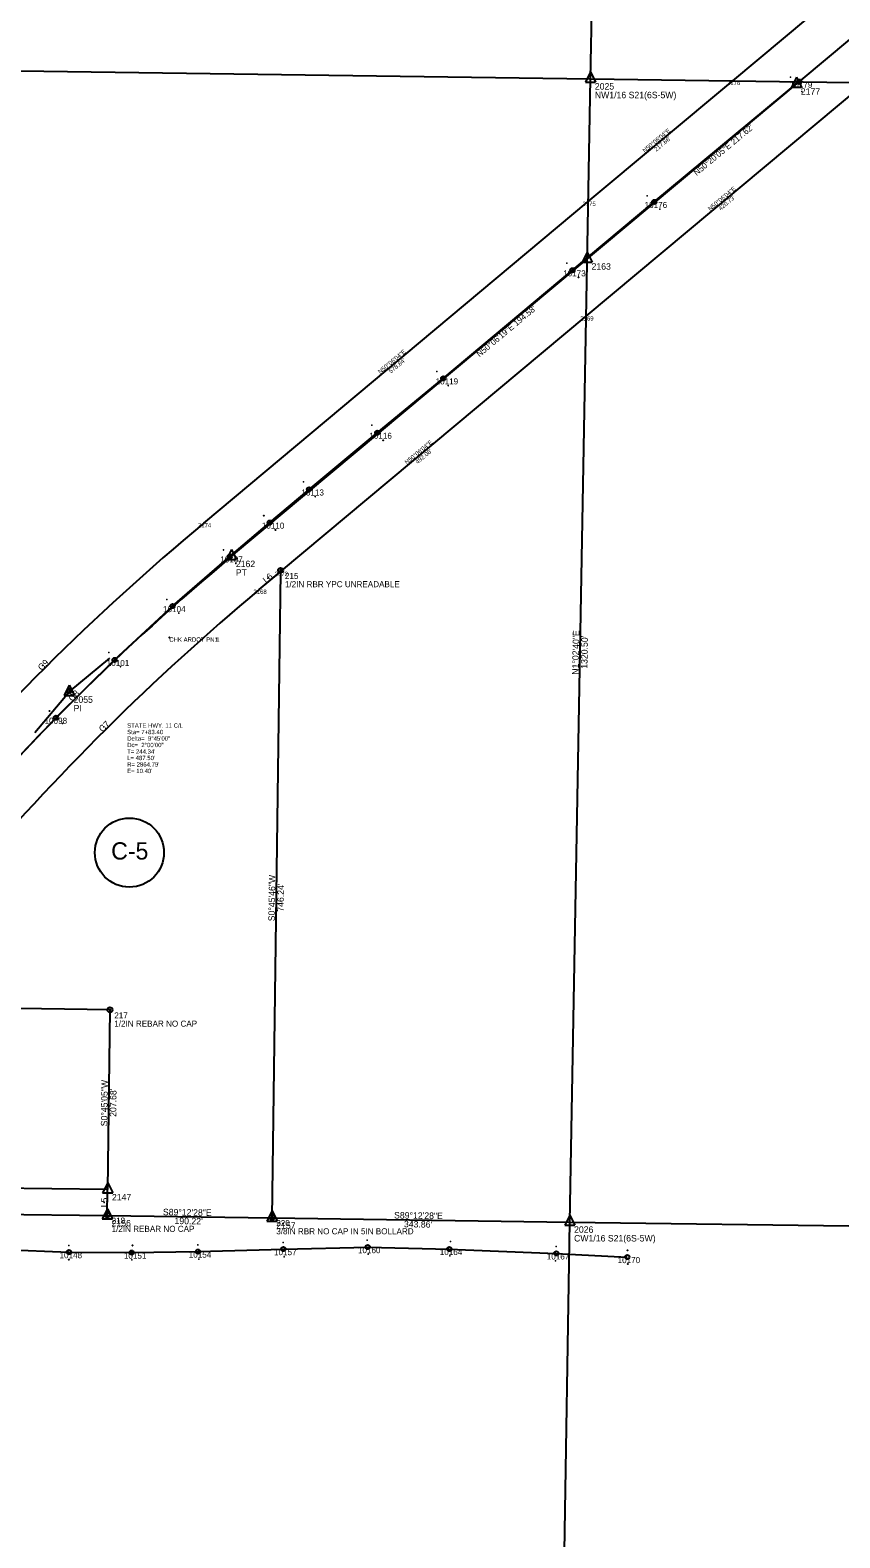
# Model space of a CAD drawing. Extents: x 1431802 to 1457777, y 1852108 to 1876350.
# Drawn here: x 1444444 to 1445379, y 1854558 to 1856299 of the extents above; entities that cross this region are included whole.
import ezdxf

# ---------------------------------------------------------------- set-up
doc = ezdxf.new("R2010")
doc.units = 0
for name, color, linetype in [('Default', 7, 'Continuous'), ('S_CAL_CORNER', 7, 'Continuous'), ('S_CAL_CORNER_ANNOT', 7, 'Continuous'), ('S_EXIST_ROW', 7, 'Continuous'), ('S_EXIST_ROW_ANNOT', 7, 'Continuous'), ('S_EXISTING_ALIGNMENT', 7, 'Continuous'), ('S_EXISTING_ALIGNMENT_ANNOT', 7, 'Continuous'), ('S_IRON_PIN', 7, 'Continuous'), ('S_IRON_PIN_ANNOT', 7, 'Continuous'), ('S_MSC_PT_SYM', 7, 'Continuous'), ('S_PROPERTY', 7, 'Continuous'), ('S_PROPERTY_ANNOT', 7, 'Continuous'), ('S_QSECTION', 7, 'Continuous'), ('S_QSECTION_ANNOT', 7, 'Continuous'), ('S_RDW_PT_SYM', 7, 'Continuous'), ('S_SIXTEEN_SECTION', 7, 'Continuous'), ('S_SIXTEEN_SECTION_ANNOT', 7, 'Continuous'), ('S_SURVEY_TEXT_ANNOT', 7, 'Continuous')]:
    doc.layers.add(name, color=color, linetype=linetype)

msp = doc.modelspace()

# ---------------------------------------------------------------- linework, layer by layer
at = {"layer": 'Default'}
for points in [[(1444718.8, 1855665.9), (1444718.8, 1855665.9), (1444718.8, 1855665.9), (1444718.8, 1855665.9), (1444718.8, 1855665.9), (1444718.8, 1855665.8), (1444718.8, 1855665.9), (1444718.8, 1855665.9)], [(1444449.8, 1855487.8), (1444489.4, 1855534.4), (1444536.3, 1855573.6)], [(1444458.9, 1855565.1), (1444458.8, 1855565.2), (1444458.9, 1855565.1), (1444458.8, 1855565.1), (1444458.9, 1855565.1), (1444458.9, 1855565.1), (1444458.9, 1855565.1), (1444458.9, 1855565.2)], [(1444494.1, 1855529.7), (1444494, 1855529.7), (1444494.1, 1855529.7), (1444494, 1855529.6), (1444494.1, 1855529.7), (1444494.1, 1855529.6), (1444494.1, 1855529.7), (1444494.1, 1855529.7)], [(1444529.3, 1855494.2), (1444529.3, 1855494.2), (1444529.3, 1855494.2), (1444529.3, 1855494.1), (1444529.3, 1855494.2), (1444529.3, 1855494.1), (1444529.3, 1855494.2), (1444529.3, 1855494.2)], [(1444529.8, 1854944.8), (1444529.7, 1854944.8), (1444529.8, 1854944.8), (1444529.8, 1854944.7), (1444529.8, 1854944.8), (1444529.8, 1854944.8), (1444529.8, 1854944.8), (1444529.8, 1854944.8)]]:
    msp.add_lwpolyline(points, dxfattribs=at)
msp.add_lwpolyline([(1444491.2, 1855532.6), (1444485.9, 1855534.4), (1444489.4, 1855537.9)], close=True, dxfattribs=at)
at = {"layer": 'S_CAL_CORNER'}
for p, q in [((1445091.5, 1856250.6), (1445085.6, 1856238.8)), ((1445091.5, 1856250.6), (1445085.6, 1856238.8)), ((1445091.5, 1856250.6), (1445097.3, 1856238.8)), ((1445091.5, 1856250.6), (1445097.3, 1856238.8)), ((1445329.4, 1856244.6), (1445323.5, 1856232.8)), ((1445329.4, 1856244.6), (1445335.2, 1856232.8)), ((1445085.6, 1856238.8), (1445097.3, 1856238.8)), ((1445085.6, 1856238.8), (1445097.3, 1856238.8)), ((1445323.5, 1856232.8), (1445335.2, 1856232.8)), ((1445087.7, 1856042.5), (1445081.8, 1856030.7)), ((1445087.7, 1856042.5), (1445093.5, 1856030.7)), ((1445081.8, 1856030.7), (1445093.5, 1856030.7)), ((1444676.9, 1855699.1), (1444671.1, 1855687.3)), ((1444671.1, 1855687.3), (1444682.7, 1855687.3)), ((1444676.9, 1855699.1), (1444682.7, 1855687.3)), ((1444489.5, 1855542.4), (1444483.6, 1855530.5)), ((1444483.6, 1855530.5), (1444495.3, 1855530.5)), ((1444489.5, 1855542.4), (1444495.3, 1855530.5)), ((1444533.8, 1854967.7), (1444527.9, 1854955.9)), ((1444527.9, 1854955.9), (1444539.6, 1854955.9)), ((1444533.8, 1854967.7), (1444539.6, 1854955.9)), ((1444533.4, 1854937.7), (1444527.5, 1854925.9)), ((1444533.4, 1854937.7), (1444539.2, 1854925.9)), ((1444723.6, 1854935.1), (1444717.7, 1854923.3)), ((1444723.6, 1854935.1), (1444729.4, 1854923.3)), ((1444527.5, 1854925.9), (1444539.2, 1854925.9)), ((1444717.7, 1854923.3), (1444729.4, 1854923.3)), ((1445067.4, 1854930.3), (1445061.6, 1854918.5)), ((1445061.6, 1854918.5), (1445073.3, 1854918.5)), ((1445067.4, 1854930.3), (1445073.3, 1854918.5))]:
    msp.add_line(p, q, dxfattribs=at)
at = {"layer": 'S_EXIST_ROW'}
for p, q in [((1445255.8, 1856240.4), (1446439.4, 1857229.9)), ((1445086.4, 1855968.4), (1445409.2, 1856238.3)), ((1445088.8, 1856100.7), (1445255.8, 1856240.4)), ((1444644.8, 1855729.5), (1445088.8, 1856100.7)), ((1444708.9, 1855652.7), (1445086.4, 1855968.4))]:
    msp.add_line(p, q, dxfattribs=at)
for radius, end in [(2914.8, 139.6489), (2814.8, 139.649)]:
    msp.add_arc((1446514.4, 1853493.3), radius, 129.899, end, dxfattribs=at)
at = {"layer": 'S_EXISTING_ALIGNMENT'}
for p, q in [((1444676.8, 1855691.1), (1446438.4, 1857164)), ((1445165, 1856100.4), (1445332.5, 1856239.3)), ((1445070.6, 1856021.4), (1445165, 1856100.4)), ((1444921.4, 1855896.6), (1445070.6, 1856021.4)), ((1444845.1, 1855833.8), (1444921.4, 1855896.6)), ((1444766.4, 1855768.3), (1444845.1, 1855833.8)), ((1444721, 1855730), (1444766.4, 1855768.3)), ((1444674.9, 1855691), (1444721, 1855730)), ((1444608.8, 1855633.6), (1444674.9, 1855691)), ((1444541.8, 1855571.4), (1444608.8, 1855633.6)), ((1444474, 1855504.7), (1444541.8, 1855571.4)), ((1444410.9, 1855438.1), (1444474, 1855504.7)), ((1444413.9, 1854890.7), (1444489, 1854887.5)), ((1444489, 1854887.5), (1444561.4, 1854886.9)), ((1444561.4, 1854886.9), (1444638.2, 1854888.1)), ((1444638.2, 1854888.1), (1444736.7, 1854891)), ((1444736.7, 1854891), (1444834.1, 1854893.3)), ((1444834.1, 1854893.3), (1444928.3, 1854891.1)), ((1444928.3, 1854891.1), (1445051.9, 1854886)), ((1445051.9, 1854886), (1445133.8, 1854881.8))]:
    msp.add_line(p, q, dxfattribs=at)
for centre in [(1445332.5, 1856239.3), (1445165, 1856100.4), (1445070.6, 1856021.4), (1444921.4, 1855896.6), (1444845.1, 1855833.8), (1444766.4, 1855768.3), (1444721, 1855730), (1444674.9, 1855691), (1444608.8, 1855633.6), (1444541.8, 1855571.4), (1444474, 1855504.7), (1444489, 1854887.5), (1444561.4, 1854886.9), (1444638.2, 1854888.1), (1444736.7, 1854891), (1444834.1, 1854893.3), (1444928.3, 1854891.1), (1445051.9, 1854886), (1445133.8, 1854881.8)]:
    msp.add_circle(centre, 2.5, dxfattribs=at)
msp.add_arc((1446514.4, 1853493.3), 2864.8, 129.899, 139.649, dxfattribs=at)
at = {"layer": 'S_IRON_PIN'}
for centre, radius in [((1444733.5, 1855674.9), 2.91), ((1444733.5, 1855674.9), 0.411), ((1444733.5, 1855674.9), 0.262), ((1444733.5, 1855674.9), 0.212), ((1444733.5, 1855674.9), 0.145), ((1444733.5, 1855674.9), 0.0581), ((1444733.5, 1855674.9), 0.0822), ((1444536.4, 1855167.4), 2.91), ((1444536.4, 1855167.4), 0.411), ((1444536.4, 1855167.4), 0.262), ((1444536.4, 1855167.4), 0.212), ((1444536.4, 1855167.4), 0.145), ((1444536.4, 1855167.4), 0.0822), ((1444536.4, 1855167.4), 0.0581), ((1444533.3, 1854930.4), 2.91), ((1444533.3, 1854930.4), 0.411), ((1444533.3, 1854930.4), 0.212), ((1444533.3, 1854930.4), 0.262), ((1444533.3, 1854930.4), 0.145), ((1444533.3, 1854930.4), 0.0581), ((1444533.3, 1854930.4), 0.0822), ((1444723.5, 1854927.6), 2.91), ((1444723.5, 1854927.6), 0.411), ((1444723.5, 1854927.6), 0.262), ((1444723.5, 1854927.6), 0.212), ((1444723.5, 1854927.6), 0.145), ((1444723.5, 1854927.6), 0.0581), ((1444723.5, 1854927.6), 0.0822)]:
    msp.add_circle(centre, radius, dxfattribs=at)
at = {"layer": 'S_MSC_PT_SYM'}
for points in [[(1444605, 1855597.4), (1444605, 1855597.5), (1444605, 1855597.4), (1444604.9, 1855597.4), (1444605, 1855597.4), (1444605, 1855597.4), (1444605, 1855597.4), (1444605, 1855597.4)], [(1444605, 1855597.4), (1444605, 1855597.5), (1444605, 1855597.4), (1444604.9, 1855597.4), (1444605, 1855597.4), (1444605, 1855597.4), (1444605, 1855597.4), (1444605, 1855597.4)], [(1444605, 1855597.5), (1444605, 1855597.5), (1444605, 1855597.5), (1444605, 1855597.5), (1444605, 1855597.5), (1444605, 1855597.4), (1444605, 1855597.5), (1444605.1, 1855597.5)]]:
    msp.add_lwpolyline(points, dxfattribs=at)
at = {"layer": 'S_PROPERTY'}
for p, q in [((1444708.9, 1855652.7), (1444733.5, 1855673.3)), ((1444733.5, 1855673.3), (1444723.5, 1854927.1)), ((1444536.4, 1855167.4), (1444279.1, 1855170.8)), ((1444536.4, 1855167.4), (1444533.7, 1854959.7)), ((1444533.7, 1854959.7), (1444276.4, 1854963.3)), ((1444533.3, 1854929.7), (1444533.7, 1854959.7)), ((1444276, 1854933.3), (1444533.3, 1854929.7)), ((1444723.5, 1854927.1), (1445067.4, 1854922.3)), ((1445067.4, 1854922.3), (1446405.8, 1854903.8))]:
    msp.add_line(p, q, dxfattribs=at)
msp.add_circle((1444558.9, 1855348.9), 39.9, dxfattribs=at)
at = {"layer": 'S_QSECTION'}
msp.add_line((1444533.3, 1854929.7), (1444723.5, 1854927.1), dxfattribs=at)
at = {"layer": 'S_RDW_PT_SYM'}
for points in [[(1445322.3, 1856244.6), (1445322.3, 1856244.6), (1445322.3, 1856244.6), (1445322.3, 1856244.6), (1445322.3, 1856244.6), (1445322.3, 1856244.5), (1445322.3, 1856244.6), (1445322.4, 1856244.6)], [(1445335.3, 1856227.9), (1445335.3, 1856227.9), (1445335.3, 1856227.9), (1445335.3, 1856227.9), (1445335.3, 1856227.9), (1445335.3, 1856227.8), (1445335.3, 1856227.9), (1445335.4, 1856227.9)], [(1445156.9, 1856107.5), (1445156.9, 1856107.6), (1445156.9, 1856107.5), (1445156.9, 1856107.5), (1445156.9, 1856107.5), (1445156.9, 1856107.5), (1445156.9, 1856107.5), (1445157, 1856107.5)], [(1445171.4, 1856092), (1445171.4, 1856092.1), (1445171.4, 1856092), (1445171.3, 1856092), (1445171.4, 1856092), (1445171.4, 1856092), (1445171.4, 1856092), (1445171.4, 1856092)], [(1445064.1, 1856029.7), (1445064.1, 1856029.8), (1445064.1, 1856029.7), (1445064.1, 1856029.7), (1445064.1, 1856029.7), (1445064.1, 1856029.7), (1445064.1, 1856029.7), (1445064.2, 1856029.7)], [(1445077.6, 1856013.2), (1445077.6, 1856013.3), (1445077.6, 1856013.2), (1445077.6, 1856013.2), (1445077.6, 1856013.2), (1445077.6, 1856013.2), (1445077.6, 1856013.2), (1445077.7, 1856013.2)], [(1444913.9, 1855904.6), (1444913.9, 1855904.6), (1444913.9, 1855904.6), (1444913.8, 1855904.6), (1444913.9, 1855904.6), (1444913.9, 1855904.5), (1444913.9, 1855904.6), (1444913.9, 1855904.6)], [(1444927.2, 1855888.3), (1444927.2, 1855888.4), (1444927.2, 1855888.3), (1444927.2, 1855888.3), (1444927.2, 1855888.3), (1444927.2, 1855888.3), (1444927.2, 1855888.3), (1444927.3, 1855888.3)], [(1444838.7, 1855842.4), (1444838.7, 1855842.5), (1444838.7, 1855842.4), (1444838.7, 1855842.4), (1444838.7, 1855842.4), (1444838.7, 1855842.4), (1444838.7, 1855842.4), (1444838.8, 1855842.4)], [(1444852, 1855825.1), (1444852, 1855825.1), (1444852, 1855825.1), (1444852, 1855825.1), (1444852, 1855825.1), (1444852, 1855825), (1444852, 1855825.1), (1444852.1, 1855825.1)], [(1444760.1, 1855777), (1444760.1, 1855777.1), (1444760.1, 1855777), (1444760, 1855777), (1444760.1, 1855777), (1444760.1, 1855777), (1444760.1, 1855777), (1444760.1, 1855777)], [(1444773.6, 1855760.3), (1444773.6, 1855760.3), (1444773.6, 1855760.3), (1444773.6, 1855760.3), (1444773.6, 1855760.3), (1444773.6, 1855760.2), (1444773.6, 1855760.3), (1444773.7, 1855760.3)], [(1444714.2, 1855738.1), (1444714.2, 1855738.1), (1444714.2, 1855738.1), (1444714.1, 1855738.1), (1444714.2, 1855738.1), (1444714.2, 1855738), (1444714.2, 1855738.1), (1444714.2, 1855738.1)], [(1444727.5, 1855721.5), (1444727.5, 1855721.5), (1444727.5, 1855721.5), (1444727.4, 1855721.5), (1444727.5, 1855721.5), (1444727.5, 1855721.4), (1444727.5, 1855721.5), (1444727.5, 1855721.5)], [(1444667.7, 1855698.6), (1444667.7, 1855698.6), (1444667.7, 1855698.6), (1444667.7, 1855698.6), (1444667.7, 1855698.6), (1444667.7, 1855698.5), (1444667.7, 1855698.6), (1444667.8, 1855698.6)], [(1444681.7, 1855682.8), (1444681.7, 1855682.9), (1444681.7, 1855682.8), (1444681.6, 1855682.8), (1444681.7, 1855682.8), (1444681.7, 1855682.8), (1444681.7, 1855682.8), (1444681.7, 1855682.8)], [(1444602.1, 1855641.2), (1444602.1, 1855641.3), (1444602.1, 1855641.2), (1444602, 1855641.2), (1444602.1, 1855641.2), (1444602.1, 1855641.2), (1444602.1, 1855641.2), (1444602.1, 1855641.2)], [(1444615.8, 1855625.6), (1444615.8, 1855625.6), (1444615.8, 1855625.6), (1444615.8, 1855625.6), (1444615.8, 1855625.6), (1444615.8, 1855625.5), (1444615.8, 1855625.6), (1444615.9, 1855625.6)], [(1444535, 1855580), (1444535, 1855580), (1444535, 1855580), (1444535, 1855580), (1444535, 1855580), (1444535, 1855579.9), (1444535, 1855580), (1444535.1, 1855580)], [(1444548.7, 1855563.9), (1444548.7, 1855564), (1444548.7, 1855563.9), (1444548.7, 1855563.9), (1444548.7, 1855563.9), (1444548.7, 1855563.9), (1444548.7, 1855563.9), (1444548.8, 1855563.9)], [(1444466.7, 1855512.5), (1444466.7, 1855512.5), (1444466.7, 1855512.5), (1444466.7, 1855512.5), (1444466.7, 1855512.5), (1444466.7, 1855512.4), (1444466.7, 1855512.5), (1444466.8, 1855512.5)], [(1444481.7, 1855498), (1444481.7, 1855498), (1444481.7, 1855498), (1444481.7, 1855498), (1444481.7, 1855498), (1444481.7, 1855497.9), (1444481.7, 1855498), (1444481.8, 1855498)], [(1444833.5, 1854901.4), (1444833.5, 1854901.4), (1444833.5, 1854901.4), (1444833.5, 1854901.4), (1444833.5, 1854901.4), (1444833.5, 1854901.3), (1444833.5, 1854901.4), (1444833.6, 1854901.4)], [(1444929.9, 1854899.9), (1444929.9, 1854899.9), (1444929.9, 1854899.9), (1444929.8, 1854899.9), (1444929.9, 1854899.9), (1444929.9, 1854899.8), (1444929.9, 1854899.9), (1444929.9, 1854899.9)], [(1444488.9, 1854895.1), (1444488.9, 1854895.2), (1444488.9, 1854895.1), (1444488.9, 1854895.1), (1444488.9, 1854895.1), (1444488.9, 1854895.1), (1444488.9, 1854895.1), (1444489, 1854895.1)], [(1444562.6, 1854895.3), (1444562.6, 1854895.4), (1444562.6, 1854895.3), (1444562.6, 1854895.3), (1444562.6, 1854895.3), (1444562.6, 1854895.3), (1444562.6, 1854895.3), (1444562.7, 1854895.3)], [(1444638, 1854895.8), (1444638, 1854895.9), (1444638, 1854895.8), (1444638, 1854895.8), (1444638, 1854895.8), (1444638, 1854895.8), (1444638, 1854895.8), (1444638.1, 1854895.8)], [(1444736.5, 1854898.7), (1444736.5, 1854898.7), (1444736.5, 1854898.7), (1444736.4, 1854898.7), (1444736.5, 1854898.7), (1444736.5, 1854898.6), (1444736.5, 1854898.7), (1444736.5, 1854898.7)], [(1444834.5, 1854885), (1444834.5, 1854885.1), (1444834.5, 1854885), (1444834.5, 1854885), (1444834.5, 1854885), (1444834.5, 1854885), (1444834.5, 1854885), (1444834.6, 1854885)], [(1444928.8, 1854883.3), (1444928.8, 1854883.4), (1444928.8, 1854883.3), (1444928.8, 1854883.3), (1444928.8, 1854883.3), (1444928.8, 1854883.3), (1444928.8, 1854883.3), (1444928.9, 1854883.3)], [(1445051.7, 1854893.9), (1445051.7, 1854894), (1445051.7, 1854893.9), (1445051.6, 1854893.9), (1445051.7, 1854893.9), (1445051.7, 1854893.9), (1445051.7, 1854893.9), (1445051.7, 1854893.9)], [(1445134.1, 1854889.5), (1445134.1, 1854889.6), (1445134.1, 1854889.5), (1445134, 1854889.5), (1445134.1, 1854889.5), (1445134.1, 1854889.5), (1445134.1, 1854889.5), (1445134.1, 1854889.5)], [(1444488.8, 1854878.9), (1444488.8, 1854878.9), (1444488.8, 1854878.9), (1444488.8, 1854878.9), (1444488.8, 1854878.9), (1444488.8, 1854878.8), (1444488.8, 1854878.9), (1444488.9, 1854878.9)], [(1444561.7, 1854878.7), (1444561.7, 1854878.7), (1444561.7, 1854878.7), (1444561.7, 1854878.7), (1444561.7, 1854878.7), (1444561.7, 1854878.6), (1444561.7, 1854878.7), (1444561.8, 1854878.7)], [(1444639, 1854879.5), (1444639, 1854879.5), (1444639, 1854879.5), (1444639, 1854879.5), (1444639, 1854879.5), (1444639, 1854879.4), (1444639, 1854879.5), (1444639.1, 1854879.5)], [(1444737.6, 1854882.2), (1444737.6, 1854882.2), (1444737.6, 1854882.2), (1444737.6, 1854882.2), (1444737.6, 1854882.2), (1444737.6, 1854882.1), (1444737.6, 1854882.2), (1444737.7, 1854882.2)], [(1445050.9, 1854877.6), (1445050.9, 1854877.6), (1445050.9, 1854877.6), (1445050.9, 1854877.6), (1445050.9, 1854877.6), (1445050.9, 1854877.5), (1445050.9, 1854877.6), (1445051, 1854877.6)], [(1445134.6, 1854873.7), (1445134.6, 1854873.8), (1445134.6, 1854873.7), (1445134.6, 1854873.7), (1445134.6, 1854873.7), (1445134.6, 1854873.7), (1445134.6, 1854873.7), (1445134.7, 1854873.7)]]:
    msp.add_lwpolyline(points, dxfattribs=at)
at = {"layer": 'S_SIXTEEN_SECTION'}
for p, q in [((1445091.4, 1856242.6), (1445115.5, 1857562.9)), ((1443941.1, 1856258.5), (1445091.4, 1856242.6)), ((1445067.4, 1854922.3), (1445091.4, 1856242.6)), ((1445091.4, 1856242.6), (1446424.8, 1856224.3)), ((1445046.7, 1853596), (1445067.4, 1854922.3))]:
    msp.add_line(p, q, dxfattribs=at)

# ---------------------------------------------------------------- texts
at = {"layer": 'Default'}
for s, p in [('STATE HWY. 11 C/L', (1444556.3, 1855493.2)), ('Sta= 7+83.40', (1444556.3, 1855485.7)), ('Delta=  9%%d45\'00"', (1444556.3, 1855478.2)), ('Dc=  2%%d00\'00"', (1444556.3, 1855470.7)), ("T= 244.34'", (1444556.3, 1855463.2)), ("L= 487.50'", (1444556.3, 1855455.7)), ("R= 2864.79'", (1444556.3, 1855448.2)), ("E= 10.40'", (1444556.3, 1855440.7))]:
    msp.add_text(s, height=5, dxfattribs=at).set_placement(p)
at = {"layer": 'S_CAL_CORNER_ANNOT'}
for s, p in [('2025', (1445096.4, 1856230.1)), ('NW1/16 S21(6S-5W)', (1445096.4, 1856220.1)), ('2177', (1445334.3, 1856224.1)), ('2163', (1445092.6, 1856022.1)), ('2162', (1444681.8, 1855678.6)), ('PT', (1444681.8, 1855668.6)), ('2055', (1444494.4, 1855521.9)), ('PI', (1444494.4, 1855511.9)), ('2147', (1444538.7, 1854947.2)), ('2156', (1444538.3, 1854917.2)), ('2157', (1444728.5, 1854914.6)), ('2026', (1445072.4, 1854909.8)), ('CW1/16 S21(6S-5W)', (1445072.4, 1854899.8))]:
    msp.add_text(s, height=7.5, dxfattribs=at).set_placement(p)
at = {"layer": 'S_EXIST_ROW_ANNOT'}
for s, p in [('2176', (1445249, 1856235.4)), ('2175', (1445082.1, 1856095.7)), ('2169', (1445079.6, 1855963.4)), ('2174', (1444638, 1855724.5)), ('2172', (1444726.7, 1855668.3)), ('2168', (1444702.1, 1855647.7))]:
    msp.add_text(s, height=5, dxfattribs=at).set_placement(p)
for s, p in [('N50%%d06\'04"E', (1445154.1, 1856156.9)), ("217.66'", (1445167.4, 1856158.3)), ('N50%%d06\'04"E', (1445229.6, 1856089.7)), ("420.73'", (1445241.8, 1856090.2)), ('N50%%d06\'04"E', (1444848.5, 1855901.5)), ("578.84'", (1444861, 1855902.1)), ('N50%%d06\'04"E', (1444879.4, 1855796.9)), ("492.08'", (1444891.7, 1855797.4))]:
    msp.add_text(s, height=5, rotation=39.899, dxfattribs=at).set_placement(p)
at = {"layer": 'S_EXISTING_ALIGNMENT_ANNOT'}
for s, p in [('10179', (1445321.6, 1856232.3)), ('10176', (1445153.9, 1856093.4)), ('10173', (1445059.8, 1856014.4)), ('10119', (1444912.5, 1855889.6)), ('10116', (1444836, 1855826.8)), ('10113', (1444757.5, 1855761.3)), ('10110', (1444711.8, 1855723)), ('10107', (1444663.8, 1855684)), ('10104', (1444597.7, 1855626.6)), ('10101', (1444532.7, 1855564.4)), ('10098', (1444460.9, 1855497.7)), ('10148', (1444478.2, 1854880.5)), ('10151', (1444552.5, 1854879.9)), ('10154', (1444627.4, 1854881.1)), ('10157', (1444725.9, 1854884)), ('10160', (1444822.8, 1854886.3)), ('10164', (1444917.3, 1854884.1)), ('10167', (1445040.9, 1854879)), ('10170', (1445122.7, 1854874.8))]:
    msp.add_text(s, height=7, dxfattribs=at).set_placement(p)
for s, rotation, p in [('N50%%d20\'05"E 217.62\'', 39.6652, (1445214, 1856130.3)), ('N50%%d06\'19"E 194.58\'', 39.8948, (1444963.2, 1855920.8))]:
    msp.add_text(s, height=7, rotation=rotation, dxfattribs=at).set_placement(p)
at = {"layer": 'S_IRON_PIN_ANNOT'}
for s, p in [('215', (1444738.5, 1855664.9)), ('1/2IN RBR YPC UNREADABLE', (1444738.5, 1855655.4)), ('217', (1444541.4, 1855157.4)), ('1/2IN REBAR NO CAP', (1444541.4, 1855147.9)), ('218', (1444538.3, 1854920.4)), ('1/2IN REBAR NO CAP', (1444538.3, 1854910.9)), ('220', (1444728.5, 1854917.6)), ('3/8IN RBR NO CAP IN 5IN BOLLARD', (1444728.5, 1854908.1))]:
    msp.add_text(s, height=7, dxfattribs=at).set_placement(p)
at = {"layer": 'S_PROPERTY'}
msp.add_text('C-5', height=19.95, dxfattribs=at).set_placement((1444537.8, 1855340.9))
at = {"layer": 'S_PROPERTY_ANNOT'}
for s, rotation, p in [('L6', 39.899, (1444716.8, 1855659.4)), ('C9', 44.7739, (1444457.5, 1855558.5)), ('C8', 44.774, (1444492.7, 1855523)), ('C7', 44.774, (1444527.9, 1855487.5)), ('S0%%d45\'46"W', 89.2371, (1444726.8, 1855269.6)), ("746.24'", 89.2371, (1444737, 1855280.6)), ('S0%%d45\'05"W', 89.2487, (1444533.4, 1855032.8)), ("207.68'", 89.2487, (1444543.6, 1855043.7)), ('L5', 89.2487, (1444533.5, 1854939.2)), ('S89%%d12\'28"E', 359.2077, (1444864.5, 1854926.4)), ("343.86'", 359.2077, (1444875.9, 1854916.2))]:
    msp.add_text(s, height=7.5, rotation=rotation, dxfattribs=at).set_placement(p)
at = {"layer": 'S_QSECTION_ANNOT'}
for s, p in [('S89%%d12\'28"E', (1444597.5, 1854930.1)), ("190.22'", (1444610.9, 1854919.9))]:
    msp.add_text(s, height=7.5, rotation=359.2077, dxfattribs=at).set_placement(p)
at = {"layer": 'S_SIXTEEN_SECTION_ANNOT'}
for s, p in [('N1%%d02\'40"E', (1445077.6, 1855554.3)), ("1320.50'", (1445087.8, 1855561.2))]:
    msp.add_text(s, height=7.5, rotation=88.9556, dxfattribs=at).set_placement(p)
at = {"layer": 'S_SURVEY_TEXT_ANNOT'}
for s, p in [('CHK ARDOT PN 1', (1444605, 1855592.4)), ('CHK ARDOT PN 1', (1444605, 1855592.4)), ('CHK ARDOT PN1', (1444605, 1855592.5))]:
    msp.add_text(s, height=5, dxfattribs=at).set_placement(p)

doc.saveas('drawing.dxf')
